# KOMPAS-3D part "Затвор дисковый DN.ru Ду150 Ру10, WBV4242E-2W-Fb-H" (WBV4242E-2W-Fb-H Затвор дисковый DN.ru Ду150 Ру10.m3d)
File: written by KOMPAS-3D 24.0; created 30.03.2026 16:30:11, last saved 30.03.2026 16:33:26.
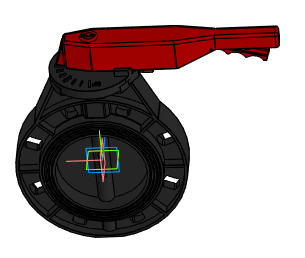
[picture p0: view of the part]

Document properties: Автор: R2D2; Полное имя файла: E:\Работа\Зайцев\WBV4242E-2W-Fb-H Затвор дисковый DN.ru Ду50-200 Ру10\DN150\WBV4242E-2W-Fb-H Затвор дисковый DN.ru Ду150 Ру10.m3d

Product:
- Part/product: Затвор дисковый DN.ru Ду150 Ру10  | designation WBV4242E-2W-Fb-H
    Масса: 5.01
    Раздел спецификации: Прочие изделия
    Примечание: D050-81202

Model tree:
1. Операция без истории:2

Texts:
  WBV4242E-2W-Fb-H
